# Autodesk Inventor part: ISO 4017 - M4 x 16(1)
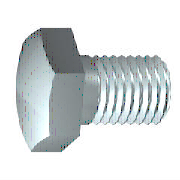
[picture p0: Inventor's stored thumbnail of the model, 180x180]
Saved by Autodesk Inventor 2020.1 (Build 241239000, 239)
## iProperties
Created: 2019-01
Part Number: ISO 4017 - M4 x 16(1)
Material: Stahl, weich
Description: Sechskantschraube
Document SubType Name: Modeling
Standard: DIN EN 24 017
Designer: lutzd
Standards Organization: DIN
Language: de-DE
Size Designation: M4 x 16
Categories: <MemberInstance><Categories><Category DisplayName="Verbindungselemente" InternalName="e4da775c-781d-43d5-af7c-5136215cf5a6" Mnemonic="FSTN"><Category DisplayNam
Mass: 2.45614 g
Surface Area: 3.46318 cm^2
Volume: 0.312884 cm^3
Density: 7.85 g/cm^3
Appearance: Halbpoliert
IsCustomPart: 0
Author: lutzd
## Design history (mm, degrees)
body "Solid1"
sketch "Skizze1"
  geometry: L1 (0, 3.015)-(0, 2); L2 (2.1, 2)-(16, 2); L3 (16, 2)-(16, 0); L4 (16, 0)-(-0.4, 0); L5 (-3.68, 0)-(19.28, 0) reference; L6 (-0.4, 0)-(-0.4, 3.015); L7 (-0.4, 3.015)-(0, 3.015); L8 (2.1, 2)-(1.67, 2); L9 (1.67, 2)-(0, 2); L10 (0, -0.603)-(0, 3.618) reference
  constraints: 16 end point, 2 collinear, 2 perpendicular, 1 parallel
  dimensions: "d0" = 16 distance between parallel lines of L3 L1 (= NLG); "d1" = 13.9 distance from line of L2.start L3 (= GEL); "d2" = 4 diameter of L2 L4 (= GD); "d9" = 0.4001 distance between parallel lines of L6 L1 (computed from SD); "d10" = 6.03 diameter of L7 L4 (= SD2); "d13" = 0.42952 distance of L2.start L8.end (computed from GAL); "d14" = 4 diameter of L9 L4 (= BDM)
workplane "Work Plane1"
revolve "Körper" stored, may be unused: angle "d12" = 90 deg
sketch "Skizze2"
  geometry: L1 (0, 4.041)-(3.5, 2.021); L2 (3.5, 2.021)-(3.5, -2.021); L3 (3.5, -2.021)-(0, -4.041); L4 (0, -4.041)-(-3.5, -2.021); L5 (-3.5, -2.021)-(-3.5, 2.021); L6 (-3.5, 2.021)-(0, 4.041); 2 further points
  constraints: 12 end point, 1 coincident, 1 vertical, 11 other
  dimensions: "d11" = 7 distance between parallel lines of L5 L2 (= SW)
extrude "Kopf" join sketch "Skizze2" distance "d3" = 2.4 (= KOH - SD); taper "d4" = 0 deg
sketch "Skizze4"
  geometry: L1 (-2.8, 3.5)-(-2.8, 4.041); L2 (-2.8, 4.041)-(-2.487, 4.041); L3 (-2.487, 4.041)-(-2.8, 3.5); L4 (-3.28, 0)-(0.08, 0) reference; L5 (-0.4, 4.041)-(-2.8, 4.041) reference; L6 (-2.8, 2.021)-(-2.8, 4.041) reference
  constraints: 6 end point, 2 collinear, 1 perpendicular, 1 vertical
  dimensions: "d5" = 30 deg angle of L3 L1 (= ANG1); "d19" = 7 diameter of L1.start L4 (= SW0)
revolve "Fase1" stored, may be unused: angle "d21" = 90 deg
feature "Gewinde" dims "d15" = 13.9 (= GEL), "d16" = 0
chamfer "Fase2" distance "d6" = 0.42941 (= -0.5 x SPD + 0.5 x GD); stored, may be unused: second distance "d7" = 0.42952 (computed from GUL), angle "d55" = 45 deg
other parameters: "NLG" = 16 [user parameter; used in 1 equation term], "GD" = 4 (= NND) [user parameter; used in 2 equation terms], "BDM" = 4 (= NND) [user parameter; used in 1 equation term], "KOH" = 2.8 [user parameter; used in 1 equation term], "GEL" = 13.9 [user parameter; used in 2 equation terms], "SW" = 7 [user parameter; used in 2 equation terms], "SW0" = 7 (= SW) [user parameter; used in 1 equation term], "SPD" = 3.14117 (= NND - 1.2269 x PTC) [user parameter; used in 1 equation term], "SD2" = 6.03 [user parameter; used in 2 equation terms], "SD" = 0.4 [user parameter; used in 2 equation terms], "ANG1" = 30 deg [user parameter; used in 1 equation term], "GAL" = 0.42941 (= 0.61345 x PTC) [user parameter; used in 1 equation term], "GUL" = 0.42941 (= 0.61345 x PTC) [user parameter; used in 1 equation term], "d8" = 0, "RR" = 0.2 [user parameter], "d57" = 0, "d58" = 0, "TPU" = 14.28571 (computed from PTC) [user parameter], "GD1" = 3.14117 (= THREADDIA - 1.2269 x PTC) [user parameter], "THREADDIA" = 4 [user parameter; used in 1 equation term], "SDH" = 6.03 (= SD2) [user parameter], "SDHG" = 2.1 [user parameter], "TOA" = 30 deg [user parameter], "PTC" = 0.7 [user parameter; used in 5 equation terms], "NND" = 4 [user parameter; used in 3 equation terms], "E0" = 8.085 [user parameter]
